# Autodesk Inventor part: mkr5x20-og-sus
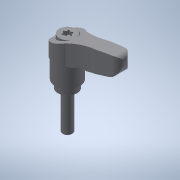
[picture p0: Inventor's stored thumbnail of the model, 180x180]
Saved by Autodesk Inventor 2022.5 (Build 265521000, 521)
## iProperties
Created: 2017-09
Part Number: mkr5x20-og-sus
Material: 一般
Document SubType Name: Modeling
Designer: imaocorp
Density: 1 g/cm^3
Appearance: 既定
Author: imaocorp
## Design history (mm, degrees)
node "mkr5x20-og-sus.x_t1"
node "mkr5x20-og-sus"
node "Base1"
